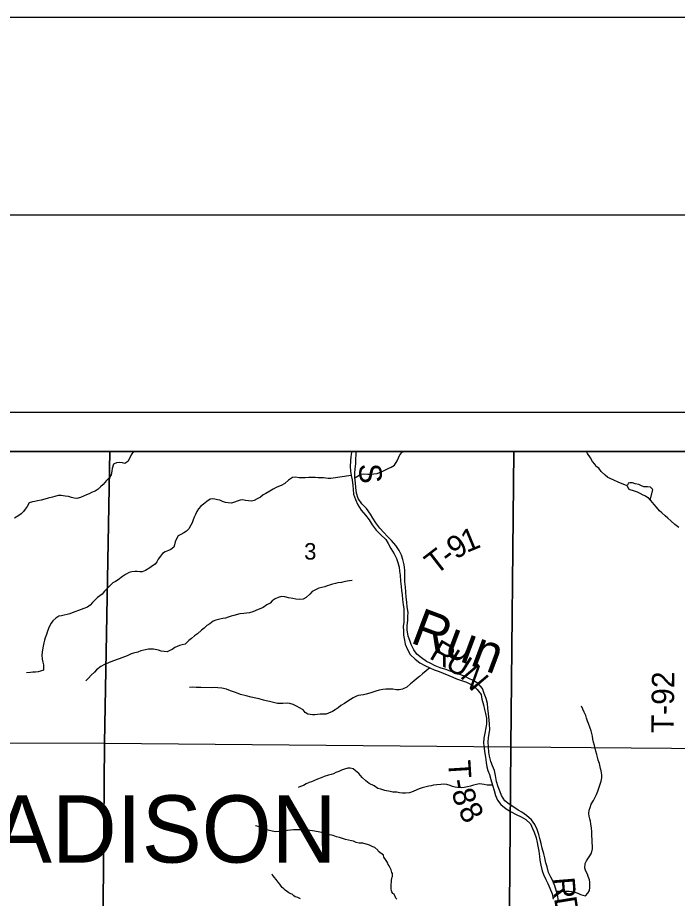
# Model space of a CAD drawing. Extents: x 0 to 34, y 0 to 22.
# Drawn here: x 4.964 to 6.637, y 19.765 to 21.998 of the extents above; entities that cross this region are included whole.
import ezdxf

# ---------------------------------------------------------------- set-up
doc = ezdxf.new("R2010")
doc.units = 0
for name, color, linetype in [('GM_X_Corporation', 7, 'Continuous'), ('GM_X_Minor_River', 7, 'Continuous'), ('GM_X_Minor_River_Text', 7, 'Continuous'), ('GM_X_Section_Text', 7, 'Continuous'), ('GM_X_Township_Road_Text', 7, 'Continuous'), ('GM_X_Township_Text', 7, 'Continuous'), ('SH_Border', 7, 'Continuous'), ('SH_Cut_Line', 7, 'Continuous'), ('SH_Data', 7, 'Continuous')]:
    doc.layers.add(name, color=color, linetype=linetype)

msp = doc.modelspace()

# ---------------------------------------------------------------- linework, layer by layer
at = {"layer": 'GM_X_Corporation'}
msp.add_lwpolyline([(8.2346, 19.7113), (8.2412, 20.0451), (8.2424, 20.1172), (8.2437, 20.1914), (8.2459, 20.3463), (8.2498, 20.6242), (8.2532, 20.898), (2.1, 20.898)], dxfattribs=at)
for points in [[(5.1975, 20.898), (4.1833, 20.898), (4.1816, 20.1598), (5.1838, 20.1584)], [(6.222, 20.898), (5.1975, 20.898), (5.1838, 20.1584), (6.2147, 20.1499)], [(7.2422, 20.898), (6.222, 20.898), (6.2147, 20.1499), (7.2322, 20.1409)], [(5.1838, 20.1584), (5.1759, 19.1377), (4.1654, 19.1412), (4.1816, 20.1598)], [(5.1838, 20.1584), (6.2147, 20.1499), (6.2057, 19.1338), (5.1759, 19.1377)], [(6.2147, 20.1499), (7.2322, 20.1409), (7.2228, 19.1563), (7.1813, 19.1288), (6.2057, 19.1338)]]:
    msp.add_lwpolyline(points, close=True, dxfattribs=at)
at = {"layer": 'GM_X_Minor_River'}
for points in [[(5.2577, 20.898), (5.2519, 20.8893), (5.2466, 20.8791), (5.2431, 20.8731), (5.2359, 20.8674), (5.2299, 20.869), (5.2227, 20.8702), (5.2144, 20.8695), (5.2064, 20.8662), (5.2033, 20.8552), (5.2029, 20.848), (5.2009, 20.8389), (5.1963, 20.8321), (5.1894, 20.8246), (5.1803, 20.8148), (5.1742, 20.8084), (5.1681, 20.8024), (5.1601, 20.7972), (5.151, 20.7938), (5.145, 20.7905), (5.1381, 20.7882), (5.1305, 20.7849), (5.123, 20.7819), (5.1135, 20.7794), (5.1074, 20.7802), (5.1007, 20.7818), (5.0927, 20.7841), (5.0844, 20.7853), (5.0738, 20.7866), (5.0663, 20.7863), (5.0579, 20.7844), (5.0519, 20.7822), (5.0413, 20.78), (5.0325, 20.7775), (5.0238, 20.7749), (5.0144, 20.7731), (5.0072, 20.7716), (5.0011, 20.7705), (4.9928, 20.7683), (4.9882, 20.7589), (4.9828, 20.7521), (4.9782, 20.7461), (4.9725, 20.7397), (4.9664, 20.7356), (4.9554, 20.7292)], [(5.8104, 20.898), (5.8102, 20.8959), (5.8089, 20.8853), (5.8079, 20.8743), (5.8072, 20.8602), (5.8081, 20.848), (5.8094, 20.8377), (5.8119, 20.8259), (5.8135, 20.8118), (5.8144, 20.8022), (5.8157, 20.79), (5.8203, 20.7762), (5.8265, 20.7632), (5.8346, 20.7497), (5.8457, 20.7365), (5.8553, 20.7246), (5.8623, 20.7123), (5.8726, 20.6987), (5.8842, 20.6878), (5.8972, 20.6747), (5.903, 20.665), (5.91, 20.652), (5.9185, 20.6389), (5.9247, 20.6266), (5.9282, 20.6166), (5.931, 20.6051), (5.9323, 20.5944), (5.9337, 20.5849), (5.9349, 20.5697), (5.9361, 20.5555), (5.9371, 20.546), (5.9384, 20.535), (5.94, 20.5227), (5.9412, 20.5094), (5.9426, 20.4999), (5.9431, 20.4881), (5.9433, 20.4782), (5.9426, 20.4649), (5.9417, 20.455), (5.9418, 20.4428), (5.9424, 20.4325)], [(5.9544, 20.4296), (5.9517, 20.4457), (5.9512, 20.4567), (5.953, 20.4696), (5.9535, 20.4799), (5.9538, 20.4901), (5.9518, 20.5043), (5.9505, 20.5165), (5.9488, 20.5287), (5.9484, 20.542), (5.9471, 20.5546), (5.9458, 20.5675), (5.9453, 20.5778), (5.9459, 20.5877), (5.9453, 20.5972), (5.9437, 20.6106), (5.9405, 20.6243), (5.937, 20.6351), (5.9308, 20.6474), (5.9223, 20.6601), (5.9119, 20.6725), (5.9015, 20.6829), (5.8919, 20.6926), (5.8818, 20.7035), (5.8722, 20.717), (5.8641, 20.7293), (5.8583, 20.739), (5.8483, 20.7536), (5.8361, 20.7657), (5.8272, 20.7791), (5.8229, 20.7929), (5.8213, 20.8067), (5.8201, 20.8185), (5.8188, 20.8311), (5.819, 20.8436), (5.8196, 20.8543), (5.821, 20.8672), (5.8216, 20.877), (5.8223, 20.8923), (5.8224, 20.898)], [(5.8188, 20.8311), (5.8343, 20.8406), (5.8404, 20.8417), (5.8521, 20.8409), (5.86, 20.8408), (5.8672, 20.8415), (5.8752, 20.8425), (5.8816, 20.8448), (5.89, 20.8481), (5.8983, 20.8522), (5.9052, 20.8559), (5.9112, 20.8582), (5.9196, 20.8634), (5.9261, 20.8743), (5.9295, 20.8819), (5.933, 20.8895), (5.9387, 20.8962), (5.9441, 20.898)], [(6.5094, 20.8107), (6.4865, 20.8206), (6.4756, 20.8252), (6.4665, 20.8295), (6.4601, 20.8322), (6.4537, 20.8384), (6.4432, 20.8472), (6.4372, 20.856), (6.4308, 20.8602), (6.4271, 20.8663), (6.4215, 20.8732), (6.4162, 20.882), (6.4091, 20.8927), (6.406, 20.898)], [(5.8094, 20.8377), (5.7575, 20.8296), (5.7514, 20.83), (5.7393, 20.8313), (5.7261, 20.8318), (5.7178, 20.8322), (5.711, 20.8323), (5.7023, 20.832), (5.6932, 20.8313), (5.6834, 20.8314), (5.6773, 20.8318), (5.6679, 20.8331), (5.6603, 20.8324), (5.6504, 20.8253), (5.6409, 20.8174), (5.6318, 20.8118), (5.6254, 20.8092), (5.6193, 20.8066), (5.6117, 20.8025), (5.6033, 20.798), (5.5935, 20.792), (5.5866, 20.7879), (5.5794, 20.7826), (5.5714, 20.7785), (5.5638, 20.7741), (5.557, 20.7726), (5.5491, 20.7727), (5.5415, 20.7743), (5.5344, 20.7755), (5.5283, 20.7748), (5.5207, 20.7722), (5.5139, 20.7696), (5.5063, 20.767), (5.4972, 20.7678), (5.4912, 20.769), (5.4829, 20.7718), (5.4765, 20.7745), (5.4704, 20.7757), (5.464, 20.7773), (5.458, 20.7785), (5.4516, 20.777), (5.4436, 20.7714), (5.4352, 20.765), (5.4284, 20.7594), (5.4223, 20.753), (5.4181, 20.7462), (5.415, 20.7382), (5.4115, 20.7314), (5.4092, 20.7246), (5.4065, 20.7174), (5.4031, 20.7114), (5.3977, 20.7023), (5.392, 20.6963), (5.3848, 20.6918), (5.3772, 20.6881), (5.3711, 20.6844), (5.3653, 20.6749), (5.3634, 20.6689), (5.3615, 20.6617), (5.3599, 20.6556), (5.3523, 20.6496), (5.3462, 20.6474), (5.3379, 20.6437), (5.3314, 20.6399), (5.3261, 20.6324), (5.3204, 20.6249), (5.3165, 20.6184), (5.3127, 20.6124), (5.3055, 20.6079), (5.2987, 20.603), (5.2876, 20.5967), (5.2797, 20.5934), (5.2732, 20.593), (5.2672, 20.5938), (5.2608, 20.5939), (5.2532, 20.5932), (5.2468, 20.5914), (5.2376, 20.5862), (5.23, 20.5813), (5.219, 20.573), (5.2118, 20.5685), (5.2053, 20.5648), (5.1955, 20.5562), (5.1836, 20.5445), (5.1779, 20.5366), (5.1661, 20.528), (5.1593, 20.5216), (5.1539, 20.5156), (5.1475, 20.5084), (5.1406, 20.5039), (5.1319, 20.4998), (5.1247, 20.4976), (5.1179, 20.495), (5.1091, 20.4921), (5.1023, 20.4891), (5.0962, 20.4865), (5.0891, 20.485), (5.0815, 20.4832), (5.0747, 20.4818), (5.0686, 20.4807), (5.0606, 20.4758)], [(6.5675, 20.7747), (6.5741, 20.8007), (6.5737, 20.803), (6.5681, 20.8076), (6.5606, 20.8082), (6.5519, 20.8087), (6.5458, 20.8107), (6.5387, 20.8143), (6.5296, 20.8164), (6.5225, 20.8188), (6.5157, 20.8189), (6.5122, 20.8175), (6.511, 20.8148), (6.5094, 20.8107), (6.5127, 20.8034), (6.5164, 20.8018), (6.5247, 20.7994), (6.5349, 20.7961)], [(6.5349, 20.7961), (6.5413, 20.7929), (6.5492, 20.7886), (6.5556, 20.7854), (6.5616, 20.7815), (6.5675, 20.7747)], [(6.64, 20.7053), (6.6306, 20.7133), (6.6204, 20.7222), (6.6125, 20.7291), (6.6054, 20.7352), (6.5971, 20.7425), (6.5911, 20.7479), (6.5836, 20.7574), (6.5776, 20.7639), (6.569, 20.7735), (6.5675, 20.7747)], [(5.8123, 20.5713), (5.8055, 20.5702), (5.7991, 20.5692), (5.7908, 20.5677), (5.7847, 20.5663), (5.7756, 20.5648), (5.7696, 20.5634), (5.7624, 20.5619), (5.7548, 20.5593), (5.7487, 20.5575), (5.7423, 20.5553), (5.7347, 20.5534), (5.7271, 20.552), (5.7173, 20.5468), (5.7108, 20.5434), (5.7047, 20.5366), (5.6952, 20.528), (5.688, 20.5239), (5.6793, 20.5228), (5.6694, 20.5237), (5.6619, 20.5253), (5.6506, 20.5269), (5.6411, 20.5293), (5.6332, 20.5309), (5.6245, 20.5279), (5.6169, 20.5249), (5.6093, 20.5197), (5.6039, 20.5133), (5.5956, 20.5092), (5.5865, 20.5024), (5.5804, 20.5002), (5.5736, 20.4972), (5.5603, 20.4921), (5.552, 20.4895), (5.5444, 20.4884), (5.5372, 20.4877), (5.527, 20.4863), (5.5118, 20.4826), (5.5054, 20.4808), (5.4974, 20.4782), (5.491, 20.4756), (5.4842, 20.4745), (5.4762, 20.4731), (5.466, 20.4705), (5.4599, 20.4679), (5.4515, 20.4612), (5.4436, 20.4567), (5.4367, 20.4503), (5.4302, 20.4454), (5.4196, 20.436), (5.4124, 20.4308), (5.4044, 20.424), (5.3979, 20.4192), (5.3884, 20.4101), (5.3808, 20.4083), (5.374, 20.4065), (5.3626, 20.4009), (5.3558, 20.3964), (5.3493, 20.3938), (5.3425, 20.3905), (5.3278, 20.3917), (5.3206, 20.3945), (5.3081, 20.3968), (5.3017, 20.3973), (5.2957, 20.397), (5.2835, 20.3944), (5.2763, 20.3926), (5.2687, 20.3896), (5.2578, 20.3871), (5.2498, 20.3841), (5.2415, 20.38), (5.2282, 20.3752), (5.2214, 20.3726), (5.2043, 20.3663), (5.1944, 20.3626), (5.1838, 20.3582), (5.1743, 20.3529), (5.164, 20.3447), (5.1583, 20.3387), (5.1503, 20.3315), (5.1431, 20.3236), (5.1366, 20.3172)], [(5.0606, 20.4758), (5.053, 20.4691), (5.0488, 20.463), (5.0457, 20.457), (5.0423, 20.4494), (5.0388, 20.44), (5.0369, 20.4339), (5.0338, 20.4256), (5.0319, 20.4195), (5.0303, 20.4127), (5.0287, 20.4048), (5.0271, 20.3957), (5.0263, 20.3896), (5.0255, 20.382), (5.0262, 20.3721), (5.0273, 20.3642), (5.0295, 20.3577), (5.0295, 20.3501), (5.029, 20.344), (5.0218, 20.3411), (5.0154, 20.3396), (5.0093, 20.3389), (5.0022, 20.3386), (4.9961, 20.3375), (4.9866, 20.3372)], [(5.9424, 20.4325), (5.9447, 20.4195), (5.9468, 20.41), (5.9526, 20.3962), (5.9592, 20.3839), (5.9715, 20.3718), (5.9834, 20.3628), (5.9965, 20.3554), (6.009, 20.3498), (6.0202, 20.345), (6.0327, 20.3402), (6.0428, 20.3362), (6.0567, 20.3306), (6.0669, 20.3258), (6.0767, 20.3218), (6.1023, 20.3137), (6.1169, 20.3054), (6.1292, 20.2945), (6.1388, 20.2822), (6.1412, 20.2699), (6.1447, 20.2558), (6.1475, 20.2439), (6.15, 20.2344), (6.1524, 20.2218), (6.1525, 20.2081), (6.1511, 20.1978), (6.1482, 20.1838), (6.1461, 20.1713), (6.145, 20.1584), (6.1463, 20.1454), (6.1487, 20.1328), (6.15, 20.1233), (6.1516, 20.1099), (6.1537, 20.0992), (6.1562, 20.0897), (6.1601, 20.079), (6.1633, 20.0663), (6.1675, 20.0522), (6.1718, 20.0388), (6.1754, 20.0262), (6.1801, 20.0146), (6.1893, 20.0034), (6.2027, 19.9921), (6.2151, 19.9847), (6.2282, 19.9776), (6.2403, 19.972), (6.2523, 19.9653), (6.2638, 19.954), (6.2696, 19.9425), (6.2736, 19.9329), (6.2783, 19.9191), (6.281, 19.9069), (6.2831, 19.8974), (6.2852, 19.8848), (6.2872, 19.8718), (6.2877, 19.8623), (6.2901, 19.8497), (6.294, 19.8351), (6.2972, 19.8256), (6.303, 19.8133), (6.3082, 19.8033), (6.3132, 19.791), (6.319, 19.7768), (6.3214, 19.7631)], [(6.3349, 19.7564), (6.3336, 19.7697), (6.3305, 19.7827), (6.3259, 19.7972), (6.3204, 19.8095), (6.3161, 19.8191), (6.3095, 19.831), (6.3063, 19.8452), (6.3031, 19.8555), (6.3004, 19.8685), (6.2979, 19.878), (6.294, 19.8922), (6.2909, 19.9048), (6.2877, 19.917), (6.2853, 19.9274), (6.2809, 19.9396), (6.2748, 19.9523), (6.267, 19.9642), (6.2544, 19.9755), (6.2424, 19.9837), (6.2326, 19.9893), (6.2195, 19.9979), (6.2098, 20.0042), (6.1994, 20.0124), (6.1909, 20.0258), (6.1869, 20.0354), (6.1819, 20.0485), (6.1776, 20.0615), (6.1753, 20.0771), (6.1725, 20.0897), (6.1682, 20.1016), (6.1638, 20.1124), (6.1603, 20.1261), (6.1582, 20.1361), (6.1578, 20.1494), (6.1572, 20.1612), (6.1575, 20.173), (6.1592, 20.1825), (6.1613, 20.1938), (6.1604, 20.2068), (6.1591, 20.2182), (6.1579, 20.2331), (6.1563, 20.2472), (6.1554, 20.259), (6.1515, 20.272), (6.1468, 20.285), (6.1422, 20.2977), (6.1314, 20.3097), (6.1191, 20.3179), (6.1082, 20.3231), (6.0984, 20.3279), (6.0848, 20.3331), (6.0717, 20.3375), (6.0604, 20.3415), (6.0498, 20.3452), (6.0351, 20.35), (6.0223, 20.3552), (6.0099, 20.3612), (6.0002, 20.3656), (5.9875, 20.3749), (5.9763, 20.3847), (5.9682, 20.3955), (5.9612, 20.4093), (5.958, 20.4189), (5.9544, 20.4296)], [(6.009, 20.3498), (5.9906, 20.3343), (5.983, 20.3279), (5.975, 20.3215), (5.9682, 20.3159), (5.9595, 20.3092), (5.9503, 20.3009), (5.9393, 20.2953), (5.931, 20.2943), (5.9242, 20.2943), (5.9147, 20.2959), (5.9053, 20.296), (5.8973, 20.2957), (5.8901, 20.2946), (5.8803, 20.2928), (5.872, 20.2902), (5.8648, 20.2884), (5.8568, 20.2855), (5.8477, 20.2829), (5.8405, 20.2814), (5.8337, 20.2807), (5.8276, 20.2797), (5.8212, 20.2771), (5.8144, 20.2737), (5.8075, 20.2692), (5.8011, 20.2651), (5.7927, 20.2595), (5.7836, 20.2539), (5.7764, 20.2482), (5.7688, 20.243), (5.7619, 20.2389), (5.7524, 20.2352), (5.746, 20.2326), (5.7399, 20.2319), (5.7305, 20.232), (5.7237, 20.2313), (5.7172, 20.2302), (5.7112, 20.2306), (5.6999, 20.2323), (5.6931, 20.2365), (5.6878, 20.2434), (5.6788, 20.2484), (5.6728, 20.2515), (5.6622, 20.2565), (5.6539, 20.2593), (5.6471, 20.2601), (5.6358, 20.2594), (5.6229, 20.2592), (5.6157, 20.2608), (5.6021, 20.2643), (5.5942, 20.2659), (5.587, 20.2675), (5.5765, 20.271), (5.5674, 20.2726), (5.5557, 20.2754), (5.5429, 20.2785), (5.5289, 20.2821), (5.5229, 20.2848), (5.5134, 20.2883), (5.5036, 20.2918), (5.4931, 20.2953), (5.4818, 20.2984), (5.4712, 20.2993), (5.4629, 20.2998), (5.4553, 20.2994), (5.4281, 20.2997), (5.4167, 20.3002), (5.4069, 20.3007), (5.3997, 20.3)], [(6.337, 19.7835), (6.3305, 19.7827), (6.3455, 19.7837), (6.352, 19.784), (6.3626, 19.7839), (6.3693, 19.7827), (6.3769, 19.7811), (6.3844, 19.7788), (6.3909, 19.7753), (6.3969, 19.7734), (6.4033, 19.7722), (6.4094, 19.7782), (6.414, 19.785), (6.4148, 19.7933), (6.4149, 19.7998), (6.4145, 19.8066), (6.4134, 19.8127), (6.4108, 19.8207), (6.409, 19.8271), (6.4049, 19.8344), (6.4023, 19.842), (6.4024, 19.8534), (6.4066, 19.8609), (6.4131, 19.8707), (6.4185, 19.8798), (6.4212, 19.8908), (6.4212, 19.8987), (6.4209, 19.906), (6.4206, 19.9151), (6.4199, 19.923), (6.4196, 19.9348), (6.4185, 19.9432), (6.4171, 19.9546), (6.416, 19.9607), (6.4146, 19.9667), (6.4127, 19.974), (6.4124, 19.9808), (6.4132, 19.9888), (6.4151, 19.996), (6.4178, 20.0039), (6.424, 20.0133), (6.4316, 20.0288), (6.4347, 20.0371), (6.4432, 20.0621), (6.4448, 20.0712), (6.4449, 20.0784), (6.4434, 20.0883), (6.4419, 20.0944), (6.439, 20.1073), (6.436, 20.1153), (6.4338, 20.1233), (6.432, 20.1302), (6.4302, 20.1385), (6.4265, 20.1526), (6.4243, 20.161), (6.4224, 20.1686), (6.421, 20.1762), (6.4195, 20.183), (6.4177, 20.1899), (6.4151, 20.1967), (6.411, 20.2085), (6.4088, 20.2146), (6.4058, 20.2219), (6.4043, 20.2291), (6.3999, 20.2371), (6.3965, 20.2451), (6.3932, 20.2527)], [(6.1675, 20.0522), (6.1542, 20.0519), (6.1471, 20.0539), (6.141, 20.0551), (6.1338, 20.0555), (6.1274, 20.0544), (6.1194, 20.0519), (6.1119, 20.05), (6.1043, 20.0478), (6.096, 20.046), (6.088, 20.0453), (6.0789, 20.0462), (6.0729, 20.0474), (6.0665, 20.0489), (6.0601, 20.0513), (6.0518, 20.054), (6.0435, 20.0545), (6.0366, 20.0541), (6.0268, 20.0531), (6.0185, 20.052), (6.0124, 20.051), (6.0064, 20.0495), (5.9897, 20.0459), (5.9817, 20.0429), (5.9757, 20.0403), (5.9669, 20.0362), (5.9571, 20.0329), (5.9476, 20.0322), (5.9397, 20.0323), (5.9317, 20.0331), (5.9253, 20.0343), (5.9151, 20.0348), (5.9083, 20.036), (5.8947, 20.0392), (5.8849, 20.0419), (5.8774, 20.0442), (5.868, 20.0504), (5.8555, 20.0562), (5.8465, 20.0631), (5.8375, 20.0719), (5.8289, 20.0815), (5.8206, 20.0888), (5.8142, 20.0938), (5.807, 20.0954), (5.801, 20.0954), (5.7926, 20.0932), (5.785, 20.0903), (5.7782, 20.0869), (5.7706, 20.084), (5.7646, 20.081), (5.7585, 20.0791), (5.7521, 20.0773), (5.7414, 20.0744), (5.7331, 20.0706), (5.7244, 20.0673), (5.7164, 20.0643), (5.7092, 20.061), (5.7028, 20.0592), (5.6952, 20.0554), (5.6883, 20.0517), (5.6811, 20.0487), (5.6747, 20.0461)], [(5.8506, 19.9022), (5.8416, 19.9045), (5.8389, 19.9049), (5.8329, 19.9054), (5.8298, 19.9054), (5.8223, 19.907), (5.8155, 19.9101), (5.8106, 19.9113), (5.7947, 19.9149), (5.7797, 19.9195), (5.7725, 19.9211), (5.7634, 19.9246), (5.7502, 19.9274), (5.7465, 19.9301), (5.7257, 19.9337), (5.7113, 19.9369), (5.7045, 19.9377), (5.6924, 19.939), (5.6807, 19.9391), (5.6629, 19.9389), (5.6557, 19.9382), (5.6406, 19.9368), (5.6364, 19.9361), (5.6319, 19.9353), (5.6293, 19.935), (5.6262, 19.9346), (5.6187, 19.9343), (5.6134, 19.9348), (5.6092, 19.9356), (5.6054, 19.9364), (5.5994, 19.9379), (5.5922, 19.9403), (5.5802, 19.9446), (5.5734, 19.9473), (5.5666, 19.9489)], [(5.9252, 19.7637), (5.9226, 19.766), (5.9182, 19.7756), (5.9155, 19.7779), (5.9125, 19.7821), (5.9114, 19.7847), (5.9111, 19.7893), (5.9112, 19.8014), (5.9116, 19.8067), (5.9116, 19.8102), (5.9128, 19.817), (5.9139, 19.8211), (5.9143, 19.8249), (5.914, 19.8284), (5.9129, 19.831), (5.911, 19.8375), (5.9084, 19.8424), (5.9054, 19.8482), (5.9032, 19.8516), (5.9028, 19.8543), (5.8998, 19.8585), (5.8969, 19.8638), (5.8927, 19.8695), (5.8913, 19.8749), (5.8789, 19.8845), (5.8774, 19.8875), (5.8695, 19.894), (5.8646, 19.896), (5.8563, 19.8999), (5.8506, 19.9022)], [(5.6418, 19.7861), (5.6388, 19.7896), (5.6347, 19.793), (5.632, 19.7961), (5.6283, 19.8011), (5.6242, 19.8064), (5.6189, 19.8129), (5.6152, 19.8179), (5.6118, 19.8221), (5.6088, 19.8255), (5.6082, 19.8265)], [(5.681, 19.7641), (5.6746, 19.7672), (5.6674, 19.7696), (5.6644, 19.7719), (5.6595, 19.7757), (5.6561, 19.7769), (5.6516, 19.7792), (5.6482, 19.7819), (5.6418, 19.7861)]]:
    msp.add_lwpolyline(points, dxfattribs=at)
at = {"layer": 'SH_Border'}
msp.add_lwpolyline([(1.5, 21.498), (33.5, 21.498), (33.5, 0.498), (1.5, 0.498)], close=True, dxfattribs=at)
at = {"layer": 'SH_Cut_Line'}
msp.add_lwpolyline([(0, -0.002), (34, -0.002), (34, 21.998), (0, 21.998)], close=True, dxfattribs=at)
at = {"layer": 'SH_Data'}
for p, q in [((2, 20.998), (9, 20.998)), ((2.1, 20.898), (8.9, 20.898))]:
    msp.add_line(p, q, dxfattribs=at)

# ---------------------------------------------------------------- texts
at = {"layer": 'GM_X_Minor_River_Text'}
msp.add_text('Run', height=0.09471, rotation=339.4218, dxfattribs=at).set_placement((5.9566, 20.4145))
at = {"layer": 'GM_X_Section_Text'}
msp.add_text('3', height=0.0419, rotation=0, dxfattribs=at).set_placement((5.6902, 20.6241))
at = {"layer": 'GM_X_Township_Road_Text'}
for s, height, rotation, p in [('S', 0.0568, 273.225, (5.8288, 20.8662)), ('1', 0.0568, 22.4083, (6.1021, 20.6407)), ('9', 0.0568, 33.3711, (6.0754, 20.6228)), ('T', 0.0568, 37.6919, (6.024, 20.5836)), ('-', 0.0568, 36.5663, (6.0574, 20.6094)), ('R', 0.0568, 329.5168, (6.0048, 20.3751)), ('U', 0.0568, 328.1329, (6.0447, 20.3516)), ('N', 0.0568, 310.2888, (6.0836, 20.3282)), ('T-92', 0.05682, 89.2891, (6.6271, 20.1838)), ('T', 0.0568, 273.5464, (6.055, 20.1141)), ('-', 0.0568, 280.486, (6.0585, 20.0642)), ('8', 0.0568, 284.9618, (6.0638, 20.0365)), ('8', 0.0568, 300.0952, (6.0791, 19.9876)), ('R', 0.0568, 274.6693, (6.3192, 19.8171)), ('D', 0.0568, 279.2163, (6.3236, 19.7658))]:
    msp.add_text(s, height=height, rotation=rotation, dxfattribs=at).set_placement(p)
at = {"layer": 'GM_X_Township_Text'}
msp.add_text('MADISON', height=0.17045, rotation=0, dxfattribs=at).set_placement((4.7086, 19.8561))

doc.saveas('drawing.dxf')
